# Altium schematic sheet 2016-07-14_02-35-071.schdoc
size 387 x 177 mm; SheetNumber: 1; SheetTotal: 1
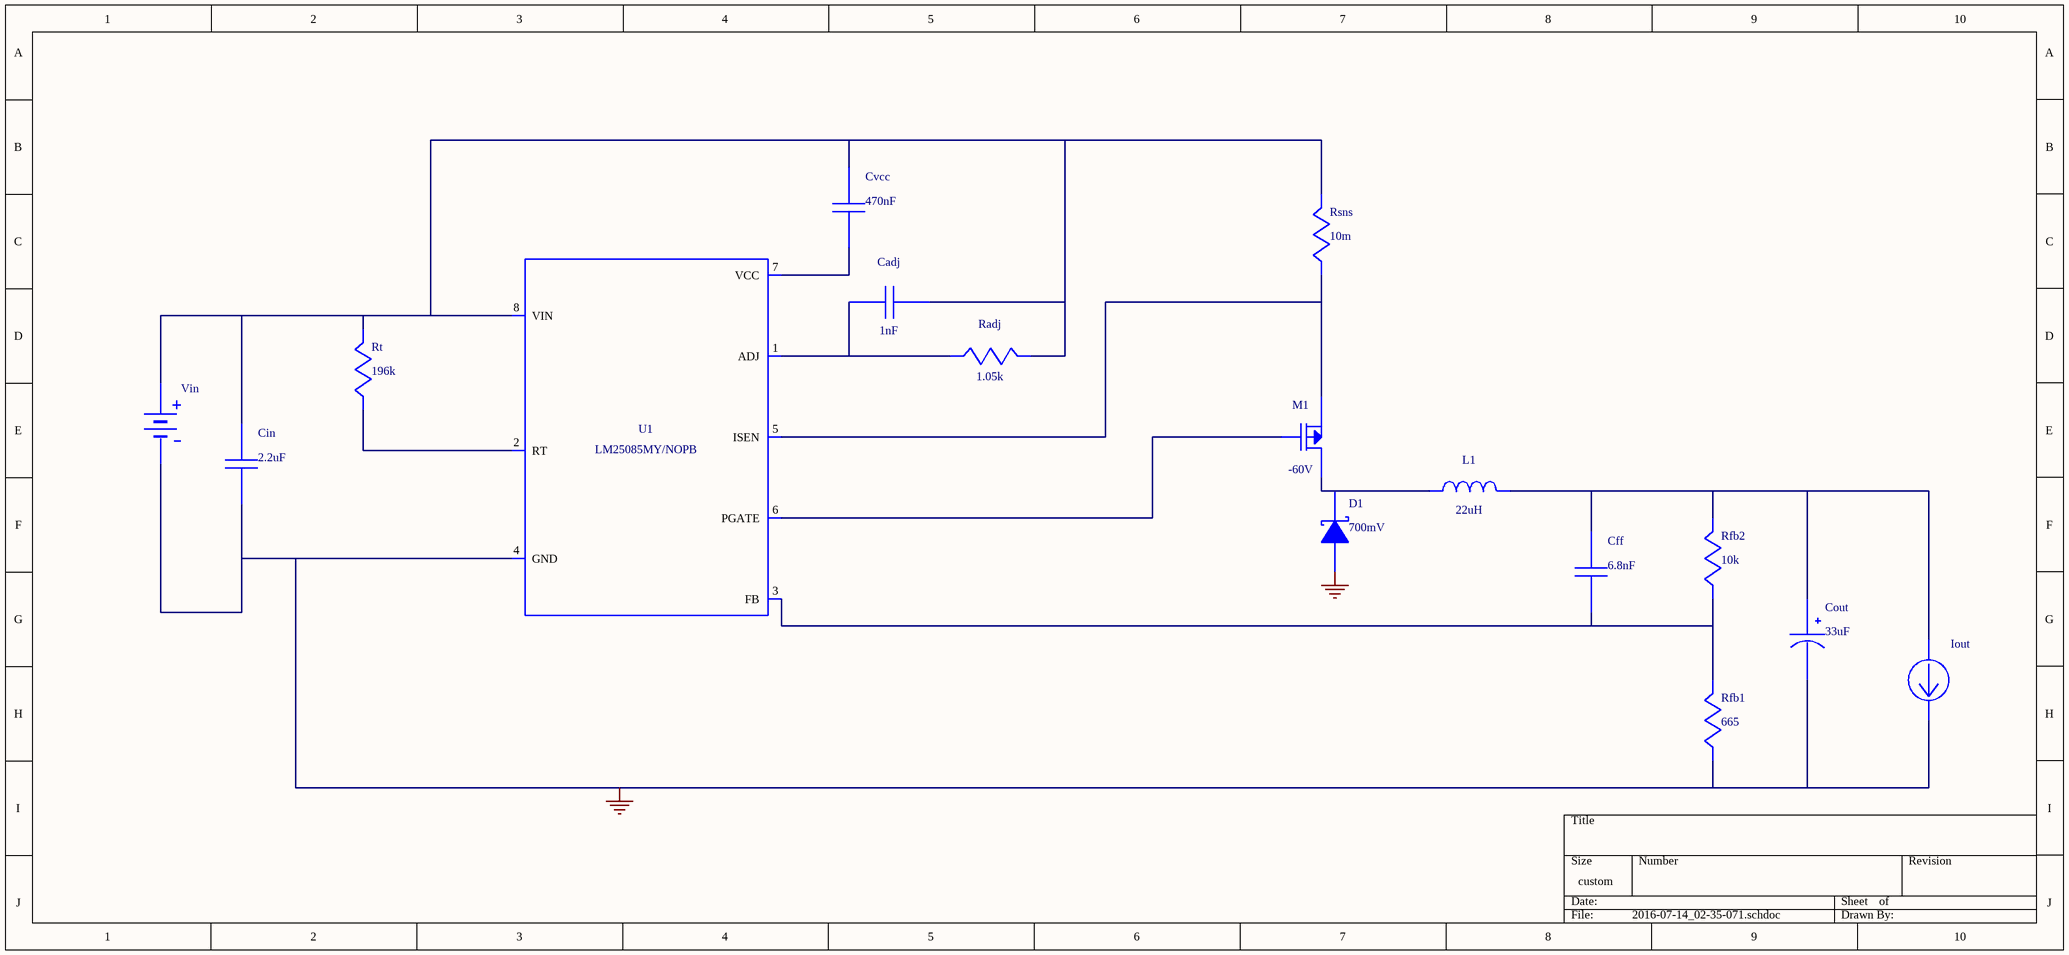
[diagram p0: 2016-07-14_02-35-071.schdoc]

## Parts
Cadj  value 1nF  (hidden comment: CL21C102JBCNFNC)
Cff  value 6.8nF  (hidden comment: GRM188R71E682KA01D)
Cin  value 2.2uF  (hidden comment: GRM31CR71H225KA88L)
Cout  value 33uF  (hidden comment: T495X336K035ATE100)
Cvcc  value 470nF  (hidden comment: 0805YC474KAT2A)
D1  value 700mV  (hidden comment: B160-13-F)
Iout  WB_CURRENT_LOAD  (value not drawn)
L1  value 22uH  (hidden comment: SDR1307-220ML)
M1  value -60V  (hidden comment: FDC5614P)
Radj  value 1.05k  (hidden comment: CRCW04021K05FKED)
Rfb1  value 665  (hidden comment: CRCW0402665RFKED)
Rfb2  value 10k  (hidden comment: CRCW040210K0FKED)
Rsns  value 10m  (hidden comment: CSR1206FK10L0)
Rt  value 196k  (hidden comment: CRCW0402196KFKED)
U1  LM5085MY/NOPB  (value not drawn)
Vin  WB_BATTERY  (value not drawn)

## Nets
0: Cin.2 Cout.2(-) D1.2(A) Iout.2(-) Rfb1.2 U1.4(GND) U1.9(EP) Vin.2(-)
NetCadj_1: Cadj.1 Cin.1 Cvcc.1 Radj.1 Rsns.1 Rt.1 U1.8(VIN) Vin.1(+)
NetCadj_2: Cadj.2 Radj.2 U1.1(ADJ)
NetCff_1: Cff.1 Cout.1(+) Iout.1(+) L1.2 Rfb2.1
NetCff_2: Cff.2 Rfb1.1 Rfb2.2 U1.3(FB)
NetCvcc_2: Cvcc.2 U1.7(VCC)
NetD1_1: D1.1(K) L1.1 M1.1(Drain) M1.2(Drain) M1.5(Drain) M1.6(Drain)
NetM1_3: M1.3(Gate) U1.6(PGATE)
NetM1_4: M1.4(Source) Rsns.2 U1.5(ISEN)
NetRt_2: Rt.2 U1.2(RT)

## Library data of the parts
Cadj = CL21C102JBCNFNC: Manufacturer Name: Samsung Electro-Mechanics
Cff = GRM188R71E682KA01D: GRM188R71E682KA0; Manufacturer Name: MuRata
Cin = GRM31CR71H225KA88L: GRM31CR71H225KA8; Manufacturer Name: MuRata
Cout = T495X336K035ATE100: T495X336K035ATE1; Manufacturer Name: Kemet
Cvcc = 0805YC474KAT2A: Manufacturer Name: AVX
D1 = B160-13-F: Manufacturer Name: Diodes Inc.
L1 = SDR1307-220ML: Manufacturer Name: Bourns
M1 = FDC5614P: Manufacturer Name: Fairchild Semiconductor
Radj = CRCW04021K05FKED: Manufacturer Name: Vishay-Dale
Rfb1 = CRCW0402665RFKED: Manufacturer Name: Vishay-Dale
Rfb2 = CRCW040210K0FKED: Manufacturer Name: Vishay-Dale
Rsns = CSR1206FK10L0: Manufacturer Name: Stackpole Electronics Inc
Rt = CRCW0402196KFKED: Manufacturer Name: Vishay-Dale
U1 = LM5085MY/NOPB: LM25085MY/NOPB; Manufacturer Name: Texas Instruments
